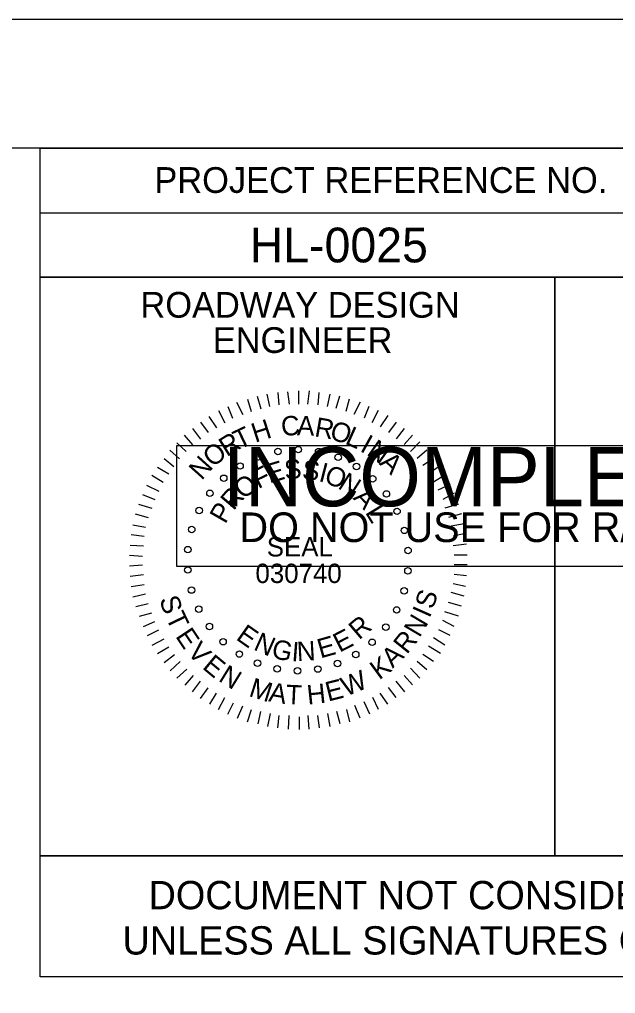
# Model space of a CAD drawing. Extents: x 1487909 to 1489267, y 497866 to 499814.
# Drawn here: x 1489029.56 to 1489041.14, y 498318.59 to 498337.52 of the extents above; entities that cross this region are included whole.
import ezdxf

# ---------------------------------------------------------------- set-up
doc = ezdxf.new("R2010")
doc.units = 0
for name, color, linetype in [('Old_Level_9', 7, 'Continuous'), ('Sheet Data Field CELL', 7, 'Continuous'), ('Sheet Plot Border Outside CELL', 7, 'Continuous'), ('Sheet Sticker Exception Certification CELL', 7, 'Continuous'), ('Sheet Sticker Incomplete CELL', 7, 'Continuous'), ('Sheet Typical CELL', 7, 'Continuous')]:
    doc.layers.add(name, color=color, linetype=linetype)

msp = doc.modelspace()

# ---------------------------------------------------------------- linework, layer by layer
at = {"layer": 'Old_Level_9'}
for p, q in [((1489034.768, 498330.282), (1489034.798, 498330.042)), ((1489034.978, 498330.302), (1489034.978, 498330.042)), ((1489035.188, 498330.302), (1489035.158, 498330.042)), ((1489033.988, 498330.142), (1489034.058, 498329.902)), ((1489034.178, 498330.202), (1489034.248, 498329.952)), ((1489034.368, 498330.242), (1489034.418, 498330.002)), ((1489034.578, 498330.272), (1489034.598, 498330.032)), ((1489035.378, 498330.272), (1489035.358, 498330.032)), ((1489035.588, 498330.242), (1489035.538, 498330.002)), ((1489035.778, 498330.202), (1489035.708, 498329.962)), ((1489035.968, 498330.142), (1489035.898, 498329.902)), ((1489033.428, 498329.922), (1489033.548, 498329.682)), ((1489033.608, 498330.002), (1489033.698, 498329.772)), ((1489033.778, 498330.082), (1489033.898, 498329.842)), ((1489036.178, 498330.082), (1489036.058, 498329.842)), ((1489036.348, 498330.002), (1489036.258, 498329.772)), ((1489036.528, 498329.922), (1489036.408, 498329.682)), ((1489033.238, 498329.802), (1489033.388, 498329.582)), ((1489036.718, 498329.822), (1489036.568, 498329.602)), ((1489032.918, 498329.572), (1489033.078, 498329.362)), ((1489033.078, 498329.692), (1489033.228, 498329.492)), ((1489036.878, 498329.692), (1489036.728, 498329.492)), ((1489037.038, 498329.572), (1489036.878, 498329.372)), ((1489032.758, 498329.442), (1489032.918, 498329.252)), ((1489037.198, 498329.442), (1489037.038, 498329.262)), ((1489032.478, 498329.152), (1489032.668, 498328.982)), ((1489032.618, 498329.292), (1489032.798, 498329.122)), ((1489037.338, 498329.312), (1489037.158, 498329.122)), ((1489037.478, 498329.152), (1489037.288, 498328.992)), ((1489032.368, 498328.992), (1489032.558, 498328.832)), ((1489037.608, 498328.992), (1489037.398, 498328.852)), ((1489032.238, 498328.822), (1489032.458, 498328.692)), ((1489037.718, 498328.832), (1489037.508, 498328.692)), ((1489032.128, 498328.662), (1489032.348, 498328.532)), ((1489037.828, 498328.662), (1489037.608, 498328.532)), ((1489032.028, 498328.472), (1489032.268, 498328.352)), ((1489037.928, 498328.482), (1489037.688, 498328.372)), ((1489031.948, 498328.292), (1489032.188, 498328.192)), ((1489038.008, 498328.312), (1489037.788, 498328.192)), ((1489031.868, 498328.102), (1489032.128, 498328.022)), ((1489038.088, 498328.102), (1489037.828, 498328.022)), ((1489031.808, 498327.912), (1489032.058, 498327.842)), ((1489038.148, 498327.912), (1489037.898, 498327.842)), ((1489031.758, 498327.702), (1489032.008, 498327.652)), ((1489038.198, 498327.722), (1489037.948, 498327.672)), ((1489031.728, 498327.512), (1489031.978, 498327.482)), ((1489038.228, 498327.532), (1489037.988, 498327.482)), ((1489031.708, 498327.302), (1489031.968, 498327.292)), ((1489038.248, 498327.322), (1489037.988, 498327.292)), ((1489031.698, 498327.112), (1489031.948, 498327.092)), ((1489038.258, 498327.112), (1489038.008, 498327.112)), ((1489031.698, 498326.902), (1489031.948, 498326.922)), ((1489038.258, 498326.922), (1489038.008, 498326.922)), ((1489031.708, 498326.702), (1489031.968, 498326.732)), ((1489038.248, 498326.712), (1489038.008, 498326.732)), ((1489031.728, 498326.502), (1489031.978, 498326.542)), ((1489038.228, 498326.502), (1489037.988, 498326.552)), ((1489031.758, 498326.302), (1489032.008, 498326.362)), ((1489038.198, 498326.312), (1489037.948, 498326.382)), ((1489031.818, 498326.112), (1489032.058, 498326.172)), ((1489038.148, 498326.122), (1489037.898, 498326.192)), ((1489031.888, 498325.922), (1489032.128, 498325.992)), ((1489038.088, 498325.922), (1489037.828, 498326.012)), ((1489031.968, 498325.722), (1489032.188, 498325.822)), ((1489038.008, 498325.722), (1489037.788, 498325.842)), ((1489032.048, 498325.552), (1489032.268, 498325.662)), ((1489037.928, 498325.552), (1489037.708, 498325.662)), ((1489032.138, 498325.362), (1489032.368, 498325.482)), ((1489037.828, 498325.362), (1489037.608, 498325.502)), ((1489032.238, 498325.202), (1489032.458, 498325.332)), ((1489032.368, 498325.022), (1489032.568, 498325.182)), ((1489037.608, 498325.042), (1489037.398, 498325.182)), ((1489037.738, 498325.202), (1489037.508, 498325.342)), ((1489032.488, 498324.862), (1489032.678, 498325.042)), ((1489037.478, 498324.882), (1489037.288, 498325.042)), ((1489032.618, 498324.722), (1489032.808, 498324.892)), ((1489037.338, 498324.722), (1489037.158, 498324.912)), ((1489032.778, 498324.582), (1489032.938, 498324.772)), ((1489032.918, 498324.452), (1489033.078, 498324.662)), ((1489037.048, 498324.452), (1489036.878, 498324.662)), ((1489037.198, 498324.592), (1489037.038, 498324.772)), ((1489033.078, 498324.322), (1489033.228, 498324.532)), ((1489033.258, 498324.212), (1489033.388, 498324.432)), ((1489036.718, 498324.212), (1489036.568, 498324.432)), ((1489036.878, 498324.342), (1489036.728, 498324.542)), ((1489033.428, 498324.112), (1489033.548, 498324.342)), ((1489033.608, 498324.022), (1489033.718, 498324.242)), ((1489036.368, 498324.022), (1489036.258, 498324.262)), ((1489036.538, 498324.112), (1489036.428, 498324.342)), ((1489033.798, 498323.942), (1489033.898, 498324.182)), ((1489033.988, 498323.872), (1489034.068, 498324.112)), ((1489034.198, 498323.832), (1489034.248, 498324.072)), ((1489034.388, 498323.782), (1489034.438, 498324.032)), ((1489035.598, 498323.782), (1489035.548, 498324.032)), ((1489035.788, 498323.832), (1489035.728, 498324.072)), ((1489035.978, 498323.872), (1489035.918, 498324.112)), ((1489036.178, 498323.942), (1489036.078, 498324.192)), ((1489034.578, 498323.752), (1489034.608, 498323.992)), ((1489034.788, 498323.732), (1489034.798, 498323.992)), ((1489034.998, 498323.722), (1489034.998, 498323.972)), ((1489035.188, 498323.732), (1489035.168, 498323.992)), ((1489035.388, 498323.752), (1489035.358, 498323.992))]:
    msp.add_line(p, q, dxfattribs=at)
for centre in [(1489034.582, 498329.126), (1489034.977, 498329.161), (1489035.372, 498329.122), (1489034.201, 498329.018), (1489035.753, 498329.012), (1489033.845, 498328.843), (1489036.108, 498328.834), (1489033.528, 498328.605), (1489036.423, 498328.594), (1489033.259, 498328.313), (1489036.689, 498328.3), (1489033.049, 498327.977), (1489036.896, 498327.962), (1489032.905, 498327.608), (1489037.038, 498327.592), (1489032.83, 498327.218), (1489037.11, 498327.202), (1489032.829, 498326.822), (1489037.108, 498326.805), (1489032.9, 498326.432), (1489037.034, 498326.416), (1489033.042, 498326.061), (1489036.889, 498326.046), (1489033.249, 498325.723), (1489036.679, 498325.71), (1489033.515, 498325.429), (1489036.411, 498325.418), (1489033.831, 498325.189), (1489036.093, 498325.18), (1489034.185, 498325.011), (1489035.738, 498325.005), (1489034.566, 498324.901), (1489034.961, 498324.863), (1489035.356, 498324.898)]:
    msp.add_circle(centre, 0.063, dxfattribs=at)
at = {"layer": 'Sheet Plot Border Outside CELL'}
msp.add_lwpolyline([(1489051.664, 498337.52), (1488883.264, 498337.52), (1488883.264, 498227.52), (1489051.664, 498227.52)], close=True, dxfattribs=at)
at = {"layer": 'Sheet Sticker Exception Certification CELL'}
for p, q in [((1489029.959, 498318.915), (1489029.959, 498321.265)), ((1489029.959, 498321.265), (1489049.962, 498321.265)), ((1489049.962, 498318.915), (1489029.959, 498318.915))]:
    msp.add_line(p, q, dxfattribs=at)
at = {"layer": 'Sheet Sticker Incomplete CELL'}
msp.add_lwpolyline([(1489032.614, 498326.89), (1489032.614, 498329.24), (1489047.314, 498329.24), (1489047.314, 498326.89)], close=True, dxfattribs=at)
at = {"layer": 'Sheet Typical CELL'}
for p, q in [((1489029.959, 498333.765), (1489049.964, 498333.765)), ((1489039.964, 498332.515), (1489039.964, 498321.27))]:
    msp.add_line(p, q, dxfattribs=at)
for points in [[(1489049.964, 498335.02), (1488899.964, 498335.02), (1488899.964, 498230.02), (1489049.964, 498230.02)], [(1489029.959, 498335.02), (1489049.964, 498335.02), (1489049.964, 498332.515), (1489029.959, 498332.515)], [(1489029.959, 498332.515), (1489039.964, 498332.515), (1489039.964, 498321.265), (1489029.959, 498321.265)], [(1489039.964, 498332.515), (1489049.964, 498332.515), (1489049.964, 498321.265), (1489039.964, 498321.265)]]:
    msp.add_lwpolyline(points, close=True, dxfattribs=at)

# ---------------------------------------------------------------- texts
at = {"layer": 'Old_Level_9'}
for s, height, rotation, p in [('H', 0.378, 17.7433, (1489034.138, 498329.292)), ('C', 0.378, 4.9399, (1489034.658, 498329.422)), ('A', 0.378, 357.9749, (1489034.948, 498329.442)), ('R', 0.378, 350.0216, (1489035.278, 498329.422)), ('O', 0.378, 343.0868, (1489035.568, 498329.372)), ('T', 0.378, 25.4358, (1489033.828, 498329.152)), ('L', 0.378, 335.7459, (1489035.868, 498329.282)), ('R', 0.378, 32.1754, (1489033.588, 498329.012)), ('I', 0.378, 330.806, (1489036.158, 498329.142)), ('N', 0.378, 324.9038, (1489036.288, 498329.072)), ('O', 0.378, 39.9442, (1489033.318, 498328.802)), ('N', 0.378, 48.0667, (1489033.098, 498328.552)), ('E', 0.376, 16.5889, (1489034.418, 498328.502)), ('S', 0.376, 4.468, (1489034.718, 498328.582)), ('S', 0.376, 353.0415, (1489035.038, 498328.592)), ('A', 0.378, 317.0051, (1489036.538, 498328.882)), ('F', 0.376, 26.4, (1489034.198, 498328.392)), ('I', 0.376, 345.4821, (1489035.358, 498328.552)), ('O', 0.376, 337.8749, (1489035.458, 498328.532)), ('O', 0.376, 38.2518, (1489033.908, 498328.182)), ('N', 0.376, 327.393, (1489035.728, 498328.422)), ('R', 0.376, 49.7478, (1489033.718, 498327.962)), ('A', 0.376, 313.9438, (1489036.028, 498328.212)), ('P', 0.376, 60.1236, (1489033.558, 498327.702)), ('L', 0.376, 301.5323, (1489036.268, 498327.942)), ('S', 0.378, 288.212, (1489032.273, 498326.254)), ('S', 0.378, 72.2579, (1489037.596, 498326.043)), ('I', 0.378, 66.0464, (1489037.526, 498325.874)), ('T', 0.378, 295.6244, (1489032.392, 498325.902)), ('N', 0.378, 59.3726, (1489037.333, 498325.494)), ('E', 0.376, 324.8692, (1489033.748, 498325.482)), ('R', 0.376, 40.3493, (1489036.158, 498325.452)), ('E', 0.378, 303.8225, (1489032.579, 498325.534)), ('N', 0.376, 336.0584, (1489034.088, 498325.282)), ('E', 0.376, 15.8057, (1489035.408, 498325.102)), ('E', 0.376, 27.1568, (1489035.778, 498325.212)), ('R', 0.378, 51.1503, (1489037.087, 498325.17)), ('V', 0.378, 311.9298, (1489032.805, 498325.216)), ('G', 0.376, 347.4812, (1489034.438, 498325.122)), ('I', 0.376, 355.6246, (1489034.838, 498325.052)), ('N', 0.376, 3.1278, (1489034.958, 498325.052)), ('E', 0.378, 320.2312, (1489033.094, 498324.919)), ('K', 0.378, 36.141, (1489036.548, 498324.676)), ('A', 0.378, 43.5217, (1489036.811, 498324.903)), ('N', 0.378, 328.329, (1489033.407, 498324.676)), ('W', 0.378, 22.0058, (1489035.903, 498324.36)), ('M', 0.378, 342.337, (1489033.998, 498324.376)), ('A', 0.378, 350.1822, (1489034.387, 498324.273)), ('H', 0.378, 6.0112, (1489035.163, 498324.206)), ('E', 0.378, 14.1648, (1489035.557, 498324.264)), ('T', 0.378, 357.3866, (1489034.728, 498324.217))]:
    msp.add_text(s, height=height, rotation=rotation, dxfattribs=at).set_placement(p)
for s, p in [('SEAL', (1489034.364, 498327.085)), ('030740', (1489034.144, 498326.569))]:
    msp.add_text(s, height=0.3759, dxfattribs=at).set_placement(p)
at = {"layer": 'Sheet Data Field CELL'}
msp.add_text('HL-0025', height=0.675, dxfattribs=at).set_placement((1489034.033, 498332.8))
at = {"layer": 'Sheet Sticker Exception Certification CELL'}
for s, p in [('DOCUMENT NOT CONSIDERED FINAL', (1489032.066, 498320.23)), ('UNLESS ALL SIGNATURES COMPLETED', (1489031.559, 498319.35))]:
    msp.add_text(s, height=0.55, dxfattribs=at).set_placement(p)
at = {"layer": 'Sheet Sticker Incomplete CELL'}
for s, height, p in [('INCOMPLETE PLANS', 1.152, (1489033.509, 498328.06)), ('DO NOT USE FOR R/W ACQUISITION', 0.576, (1489033.834, 498327.365))]:
    msp.add_text(s, height=height, dxfattribs=at).set_placement(p)
at = {"layer": 'Sheet Typical CELL'}
for s, height, p in [('PROJECT REFERENCE NO.', 0.50001, (1489032.179, 498334.15)), ('ROADWAY DESIGN', 0.50001, (1489031.909, 498331.725)), ('ENGINEER', 0.5, (1489033.314, 498331.04))]:
    msp.add_text(s, height=height, dxfattribs=at).set_placement(p)

doc.saveas('drawing.dxf')
